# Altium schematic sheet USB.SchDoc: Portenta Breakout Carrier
size A4; Author: Ernesto Lopez; DocumentNumber: ASX00031; Revision: V1.3; SheetNumber: 4; SheetTotal: 6; RevAuthor: Silvio Navaretti
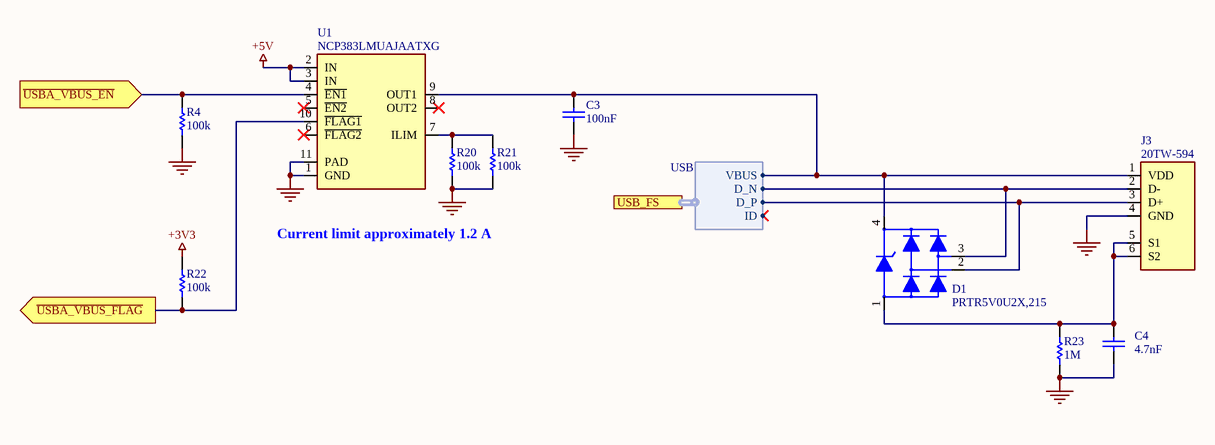
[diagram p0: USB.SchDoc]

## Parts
C3  value 100nF  [CAP-0402]  (hidden comment: C0402C104K3PACTU)
C4  value 4.7nF  [CAP-0805]  (hidden comment: C0805C472KDRACTU)
D1  PRTR5V0U2X,215  [SOT190P230X110-4N]
J3  20TW-594  [20TW595-Footprint-1]
R4  value 100k  [RES-0402]  (hidden comment: CRCW0402100KFKEDC)
R20  value 100k  [RES-0402]  (hidden comment: CRCW0402100KFKEDC)
R21  value 100k  [RES-0402]  (hidden comment: CRCW0402100KFKEDC)
R22  value 100k  [RES-0402]  (hidden comment: CRCW0402100KFKEDC)
R23  value 1M  [RES-0402]  (hidden comment: CRCW04021M00FKED)
U1  NCP383LMUAJAATXG  [PQFN50P300X300X55_HS-21L]

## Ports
USB_FS (harness USB), ~{USBA_VBUS_EN} (in), ~{USBA_VBUS_FLAG} (out)

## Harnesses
USB: VBUS, D_N, D_P, ID

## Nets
+3V3: R22.1
+5V: U1.2(IN) U1.3(IN)
GND: C3.2 C4.1 J3.4(GND) R4.2 R20.2 R21.2 R23.1 U1.1(GND) U1.11(PAD)
~{USBA_VBUS_EN}: R4.1 U1.4(~{EN1}) ; port ~{USBA_VBUS_EN}
~{USBA_VBUS_FLAG}: R22.2 U1.10(~{FLAG1}) ; port ~{USBA_VBUS_FLAG}
NetC3_1: C3.1 D1.4 J3.1(VDD) U1.9(OUT1) ; port USB_FS.VBUS
NetC4_2: C4.2 D1.1 J3.5(S1) J3.6(S2) R23.2
NetD1_2: D1.2 J3.3(D+) ; port USB_FS.D_P
NetD1_3: D1.3 J3.2(D-) ; port USB_FS.D_N
NetR20_1: R20.1 R21.1 U1.7(ILIM)

Not connected (* = marked no-connect by the designer): U1 5(~{EN2})* 6(~{FLAG2})* 8(OUT2)*

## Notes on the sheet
- Current limit approximately 1.2 A

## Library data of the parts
C3 = C0014-A.9: CAP CHIP 0402 100nF 25V X5R 10%; Manufacturer: KEMET; Code Arduino: 0132
C4 = C0059-A.9: CAP CHIP 0805 4.7nF 1000V X7R 10%; Manufacturer: KEMET; Voltage: 1kV; Code Arduino: 0689
D1 = D0025-A.3: TVS ARRAY 4LIN.8kV 1pF SOT143B; Manufacturer: Nexperia; Device Type: ESD protection; Code Arduino: 2209
J3 = J0135-A.4: CONN USB A VERTICAL; Manufacturer: 4UCON; Code Arduino: J0135
R4 R20-R22 = R0001-A.5: RES CHIP 0402 100K 1% 1/16W; Manufacturer: Vishay; Power: 63mW; Code Arduino: 0134
R23 = R0058-A.5: RES CHIP 0402 1M 1% 1/16W; Manufacturer: Vishay; Power: 63mW; Code Arduino: 0139
U1 = U0052-A.5: IC POWER SWITCH DUAL CHANNEL OCP; Manufacturer: ON Semiconductor; Max Input Voltage: 5.5V; Min Input Voltage: 2.7V; Turn-Off Delay Time: 3ms; Number of Outputs: 2; Output Configuration: High Side; Turn-On Delay Time: 9ms; Interface: On/Off; Max Power Dissipation: 850mW; Code Arduino: U0052; On-State Resistance: 95mR; Max Output Current: 2.5A; Device Type: PWR SWITCH; Fault Protection: Over Temperature; Max Supply Current: 1uA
